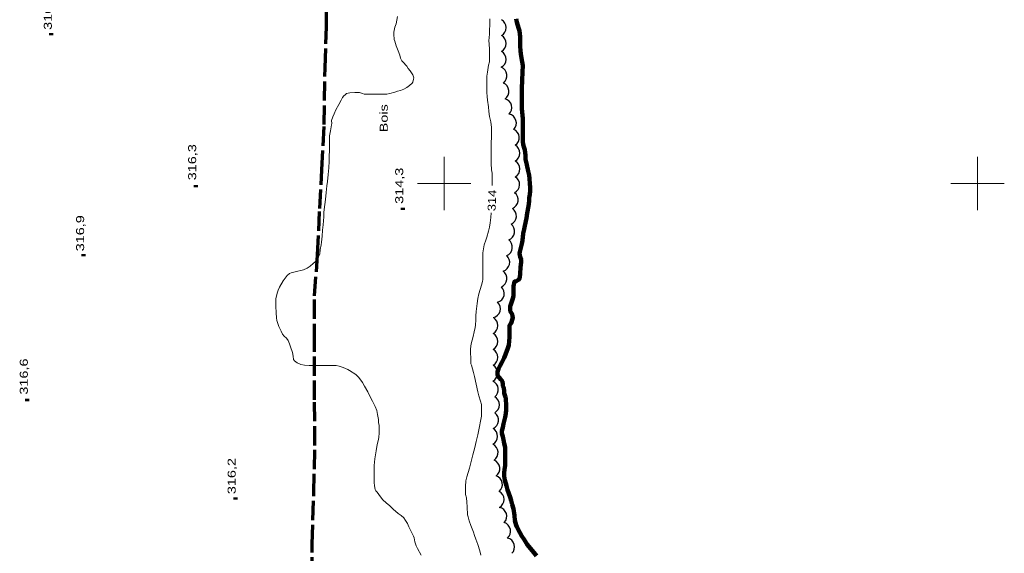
# Model space of a CAD drawing. Extents: x 240591 to 242335, y 5323482 to 5326937.
# Drawn here: x 241641 to 242010, y 5325061.4 to 5325261.4 of the extents above; entities that cross this region are included whole.
import ezdxf
from ezdxf.enums import TextEntityAlignment as Align

# ---------------------------------------------------------------- set-up
doc = ezdxf.new("R2010")
doc.units = 0
doc.header["$LTSCALE"] = 1.2
doc.linetypes.add('DASH_DOUBLE_DOT', pattern=[9.2, 5, -1.2, 0.3, -1.2, 0.3, -1.2])
doc.linetypes.add('LONG_DASHED', pattern=[7.5, 6, -1.5])
for name, color, linetype, lineweight in [('2', 7, 'Continuous', 13), ('22', 7, 'LONG_DASHED', 70), ('3', 7, 'Continuous', 140), ('4', 7, 'DASH_DOUBLE_DOT', 53), ('44', 7, 'Continuous', 25), ('61', 7, 'Continuous', 13)]:
    doc.layers.add(name, color=color, linetype=linetype, lineweight=lineweight)

msp = doc.modelspace()

# ---------------------------------------------------------------- linework, layer by layer
at = {"layer": '2', "linetype": 'LONG_DASHED'}
for points in [[(241782.5, 5325262.6), (241782.3, 5325261.3), (241782, 5325259.9), (241781.6, 5325258.6), (241781.2, 5325256.7), (241781.2, 5325256), (241781.3, 5325254), (241781.5, 5325253.4), (241782.1, 5325251.6), (241782.8, 5325249.8), (241783.4, 5325248.1), (241783.7, 5325247), (241784.2, 5325246), (241784.5, 5325245.6), (241786, 5325244), (241786.6, 5325243.1), (241787.3, 5325242.2), (241788.3, 5325240.7), (241788.7, 5325239.6), (241788.6, 5325239.1), (241788.3, 5325238), (241788, 5325237.6)], [(241817.2, 5325261.7), (241817.2, 5325259.2), (241817.1, 5325257.8), (241817, 5325256), (241816.8, 5325253.5), (241816.9, 5325252.4), (241817, 5325250.3), (241817, 5325248.3), (241817, 5325245.6), (241816.7, 5325244.4), (241816.3, 5325241.8), (241816.1, 5325240.3), (241816.1, 5325239), (241816.1, 5325237.1), (241816.1, 5325234.1), (241816.2, 5325232.6), (241816.3, 5325231.3), (241816.7, 5325228.8), (241816.8, 5325227), (241817.1, 5325225.1), (241817.5, 5325223.1), (241817.8, 5325221), (241817.8, 5325220.1), (241817.8, 5325217.5), (241817.7, 5325215.2), (241817.7, 5325213.4), (241817.7, 5325210.5), (241817.7, 5325207.5), (241817.8, 5325205.1), (241818, 5325203.9), (241818, 5325202.3), (241818, 5325199.7), (241818, 5325199.3)], [(241788, 5325237.6), (241787.1, 5325236.8), (241786, 5325236), (241784.9, 5325235.4), (241783.7, 5325234.9), (241782.5, 5325234.6), (241781.5, 5325234.3), (241779.7, 5325233.8), (241778.6, 5325233.5), (241777.4, 5325233.5), (241775.4, 5325233.5), (241772.6, 5325233.5), (241770.1, 5325233.5), (241769.4, 5325233.7), (241768.3, 5325234.1), (241767.6, 5325234.1), (241766.6, 5325234.1), (241764.7, 5325234), (241763.5, 5325233.7), (241762.9, 5325233.3), (241762.5, 5325232.9), (241762, 5325232.2), (241761.4, 5325231.2), (241760.6, 5325229.6), (241759.5, 5325227.7), (241758.8, 5325226.1), (241758.3, 5325225), (241757.8, 5325223.7)], [(241757.8, 5325223.7), (241757.9, 5325222.5), (241757.8, 5325222), (241757.5, 5325219.8), (241757.1, 5325217.9), (241757.1, 5325217), (241757.1, 5325215.2), (241757.1, 5325212.5), (241757, 5325210.1), (241756.9, 5325208.4), (241756.8, 5325205.9), (241756.6, 5325203.4), (241756.3, 5325200.8), (241756.1, 5325199.2), (241755.8, 5325196.6), (241755.6, 5325194), (241755.3, 5325192.1), (241755, 5325189.3), (241754.9, 5325187.6), (241754.7, 5325184.6), (241754.4, 5325182.5), (241754.3, 5325180.3), (241754.1, 5325178), (241753.9, 5325177.1), (241753.6, 5325175.3), (241753.4, 5325173.7), (241753, 5325172.6), (241752.5, 5325171.6), (241751.7, 5325170.7), (241750.9, 5325170), (241749.8, 5325169.1), (241748.7, 5325168.3), (241747.3, 5325167.7), (241746.3, 5325167.4), (241745.2, 5325167.2), (241742.7, 5325166.6), (241742.1, 5325166.3), (241741.2, 5325165.6), (241740.4, 5325164.6), (241739.7, 5325163.5), (241738.3, 5325161.2), (241737.8, 5325160), (241737.5, 5325158.9), (241737, 5325156.8), (241737, 5325155.5), (241737, 5325154), (241737.1, 5325151.5), (241737.2, 5325149.7), (241737.3, 5325148.7), (241737.7, 5325147.6), (241738.1, 5325146.4), (241738.9, 5325144.7), (241739.5, 5325143.6), (241740.1, 5325142.8), (241740.9, 5325142.1), (241741.6, 5325141.2), (241742.1, 5325140), (241742.5, 5325138.8), (241743.2, 5325136.7), (241743.4, 5325135.3), (241743.6, 5325134.1), (241744, 5325133.6), (241745, 5325132.8), (241746.3, 5325132.2), (241747.7, 5325131.9), (241749.4, 5325131.8), (241750.8, 5325131.8), (241754, 5325131.8), (241756.8, 5325131.8), (241759.6, 5325131.8), (241760.7, 5325131.6), (241762.2, 5325131.1), (241764, 5325130.3), (241764.6, 5325129.9), (241766.9, 5325128.4), (241768, 5325127.4), (241768.5, 5325126.8), (241769.4, 5325125.5), (241770.2, 5325124.1), (241771.4, 5325121.9), (241772.1, 5325120.6), (241773.2, 5325118.5), (241774.2, 5325116.4), (241774.8, 5325115), (241775.1, 5325113.5), (241775.4, 5325111.6), (241775.5, 5325110.5), (241775.7, 5325109.4), (241775.7, 5325108.1), (241775.7, 5325106.6), (241775.6, 5325104.8), (241775.3, 5325103.6), (241775, 5325102.2), (241774.6, 5325099.9), (241774.1, 5325096.8), (241773.8, 5325094.4), (241773.8, 5325093.5), (241773.8, 5325090.8), (241773.8, 5325088), (241773.9, 5325086.7), (241774.2, 5325085.4)], [(241817.7, 5325189), (241817.5, 5325187.3), (241817.3, 5325185.3), (241817, 5325183.7), (241816.7, 5325182.2), (241816.1, 5325179.9), (241815.7, 5325178.8), (241815.1, 5325177), (241814.8, 5325175.5), (241814.6, 5325174), (241814.6, 5325172.3), (241814.6, 5325169.7), (241814.6, 5325167), (241814.6, 5325164), (241814.4, 5325163.3), (241814, 5325161.9), (241813.1, 5325158.7), (241812.7, 5325156.9), (241812.4, 5325155), (241812, 5325152.1), (241811.9, 5325150.4), (241811.9, 5325148.9), (241811.8, 5325146.9), (241811.7, 5325146.1), (241811.3, 5325144.5), (241810.9, 5325142.7), (241810.2, 5325140), (241809.9, 5325138.1), (241809.9, 5325137.1), (241810, 5325134.1), (241810.1, 5325132.5), (241810.3, 5325131.9), (241811.1, 5325129.2), (241811.4, 5325127.7), (241812, 5325124.8)], [(241812, 5325124.8), (241812.7, 5325121.9), (241813.1, 5325120.4), (241813.7, 5325118.4), (241814, 5325117.2), (241814.1, 5325116), (241814.1, 5325114.5), (241814, 5325112.8), (241813.7, 5325110.9), (241813.3, 5325109), (241812.7, 5325105.9), (241812.1, 5325103.3), (241811.6, 5325101.1), (241810.8, 5325098.3), (241810.2, 5325095.8), (241809.5, 5325093.3), (241809, 5325091.7), (241808.5, 5325090.1), (241808.2, 5325088.6), (241808, 5325086.5), (241808, 5325085.3), (241808.1, 5325083.5), (241808.4, 5325082.2), (241808.6, 5325080.6), (241808.7, 5325078.9), (241808.8, 5325075.9), (241809, 5325075.1), (241809.4, 5325073.6), (241810, 5325071.8), (241810.6, 5325070.6), (241811.1, 5325069.4), (241811.4, 5325068.1), (241811.9, 5325066.8), (241812.7, 5325064.7), (241813.4, 5325062.4), (241813.8, 5325060.7)], [(241774.2, 5325085.4), (241774.5, 5325084.9), (241774.9, 5325084.3), (241776.2, 5325082.6), (241777.1, 5325081.5), (241778.3, 5325080.4), (241779.7, 5325079.2), (241781, 5325078), (241782.8, 5325076.4), (241783.9, 5325075.6), (241784.9, 5325074.7), (241785.6, 5325073.7), (241786.3, 5325072.6), (241786.8, 5325071.4), (241787.9, 5325069.1), (241788.6, 5325067.9), (241788.8, 5325067.2), (241789.1, 5325065.7), (241789.5, 5325064.3), (241790.1, 5325063.2), (241791.4, 5325060.7)]]:
    msp.add_lwpolyline(points, dxfattribs=at)
at = {"layer": '22'}
msp.add_lwpolyline([(241750.3, 5325043.8), (241750.6, 5325064.9), (241751.2, 5325084), (241751.6, 5325101.9), (241751.5, 5325119), (241751.4, 5325140.3), (241751.5, 5325157.9), (241752.6, 5325173.3), (241753.4, 5325190.6), (241754.2, 5325205.2), (241755.1, 5325222.1), (241755.4, 5325243.4), (241756, 5325258.8), (241756, 5325268.5)], dxfattribs=at)
at = {"layer": '3'}
for p, q in [((241652.8, 5325255.6), (241652.8, 5325256.4)), ((241707, 5325198.6), (241707, 5325199.4)), ((241784.5, 5325190.1), (241784.5, 5325190.9)), ((241664.9, 5325172.8), (241664.9, 5325173.6)), ((241643.8, 5325118.5), (241643.8, 5325119.3)), ((241721.8, 5325081.6), (241721.8, 5325082.4))]:
    msp.add_line(p, q, dxfattribs=at)
at = {"layer": '4', "linetype": 'Continuous', "lineweight": 90}
for points in [[(241824.5, 5325144.6), (241824.5, 5325146.4), (241824.6, 5325147), (241825, 5325147.5), (241825.3, 5325148.1), (241825.8, 5325149.8), (241825.7, 5325150.3), (241825.5, 5325151), (241824.8, 5325152.2), (241824.8, 5325152.7), (241824.8, 5325154), (241825, 5325154.7), (241825.7, 5325156.5), (241826, 5325157.8), (241826, 5325159), (241826, 5325161.6), (241826.4, 5325163.3), (241827, 5325163.4), (241827.9, 5325163.9), (241828.3, 5325164.4), (241828.4, 5325164.9), (241828.5, 5325166.2), (241828.7, 5325168.7), (241828.9, 5325170.5), (241828.9, 5325171.6), (241828.6, 5325172.5), (241828.3, 5325173.8), (241828.4, 5325174.4), (241828.5, 5325174.9), (241829.2, 5325177.4), (241829.4, 5325178.7), (241829.7, 5325181.3), (241830, 5325182.9), (241830.3, 5325184.2), (241830.9, 5325187), (241831.2, 5325188.9), (241831.7, 5325191.5), (241831.9, 5325193.4), (241831.9, 5325194.6), (241832.2, 5325195.9), (241832.3, 5325197.3), (241832.3, 5325198.7), (241832.1, 5325199.9), (241832, 5325201.9), (241831.9, 5325203.2), (241831.5, 5325204.7), (241831, 5325207), (241830.5, 5325209.1), (241830.5, 5325210.5), (241830.3, 5325212.7), (241830, 5325213.4), (241829.7, 5325214.6), (241829.6, 5325215.8), (241829.6, 5325217), (241829.6, 5325220.2), (241829.6, 5325222.9), (241829.5, 5325224.3), (241829.4, 5325225.7), (241829.2, 5325228), (241829.2, 5325229.7), (241829.2, 5325232.8), (241829.2, 5325235.6), (241829.3, 5325238.7), (241829.4, 5325241.7), (241829.5, 5325244.3), (241829.3, 5325245.6), (241828.8, 5325248.5), (241828.7, 5325249.9), (241828.6, 5325251.4), (241828.6, 5325252.8), (241828.6, 5325255), (241828.3, 5325257.3), (241827.9, 5325258.4), (241827.3, 5325260.5), (241827.1, 5325261.7)], [(241834.6, 5325060.5), (241833.7, 5325061.7), (241832.4, 5325063.3), (241831.2, 5325064.8), (241830, 5325066.6), (241829.2, 5325067.9), (241828.4, 5325069.2), (241827.3, 5325071.3), (241827, 5325072), (241826.6, 5325073.7), (241826.4, 5325075.6), (241826, 5325078.1), (241825.6, 5325079.7), (241825.2, 5325081.2), (241824.8, 5325082.5), (241823.8, 5325085.2), (241823.4, 5325086.7), (241822.8, 5325088.9), (241822.6, 5325090.3), (241822.5, 5325091.6), (241822.7, 5325092.9), (241822.9, 5325094.4), (241822.9, 5325095.8), (241822.9, 5325098.4), (241822.9, 5325101.2), (241822.6, 5325102.6), (241822.3, 5325104), (241822, 5325105.2), (241821.7, 5325106.3), (241821.7, 5325107.4), (241822, 5325108.6), (241822.3, 5325109.9), (241822.9, 5325112.4), (241823.2, 5325113.8), (241823.3, 5325115.2), (241823.3, 5325116.7), (241823.2, 5325119.4), (241823, 5325119.9), (241822.5, 5325121.5), (241822.5, 5325122.2), (241822.4, 5325123.5), (241822.1, 5325124.1), (241822, 5325124.7), (241821.9, 5325125.8), (241821.7, 5325126.2), (241821.3, 5325126.6), (241820.1, 5325128.1), (241820, 5325128.8), (241820, 5325129.4), (241820.4, 5325130.6), (241821, 5325131.8), (241821.7, 5325133), (241822.6, 5325134.7), (241823.1, 5325135.9), (241823.9, 5325138.3), (241824.3, 5325139.5), (241824.4, 5325140.9), (241824.5, 5325142.4), (241824.5, 5325144.6)]]:
    msp.add_lwpolyline(points, dxfattribs=at)
at = {"layer": '44'}
for centre, radius, start, end in [((241822.044, 5325228.477), 3.397, 313.67077, 75.75749), ((241824.94, 5325199.63), 3.403, 296.72203, 58.45794), ((241824.432, 5325193.87), 3.399, 291.17613, 53.16333), ((241816.766, 5325134.895), 3.404, 299.0688, 60.93119), ((241819.098, 5325081.602), 3.413, 300.11391, 61.80858), ((241820.117, 5325075.322), 3.399, 316.44032, 78.2332), ((241821.565, 5325069.729), 3.406, 310.79091, 72.65931), ((241823.044, 5325063.829), 3.404, 315.44062, 77.34933)]:
    msp.add_arc(centre, radius, start, end, dxfattribs=at)
for centre, major_axis, ratio, start_param, end_param in [((241819.874, 5325258.45), (3.396, 0), 0.999909, 5.2183457, 7.3480249), ((241819.862, 5325252.505), (3.401, -0.222), 0.999115, 5.2854962, 7.4108615), ((241819.84, 5325246.574), (3.4, -0.048), 0.999859, 5.219818, 7.3515117), ((241820.198, 5325240.418), (3.371, 0.458), 0.999638, 5.2175023, 7.3421705), ((241820.916, 5325234.55), (3.385, 0.369), 0.999797, 5.2189869, 7.3491912), ((241823.699, 5325222.676), (3.262, 1.01), 0.99986, 5.2212193, 7.3501784), ((241824.798, 5325217.213), (-1.981, 2.759), 0.999995, 3.1135274, 5.2446031), ((241825.04, 5325211.433), (3.4, 0), 0.999977, 5.2191058, 7.3438982), ((241825.046, 5325205.487), (3.404, 0.029), 0.997501, 5.2179345, 7.3413801), ((241823.737, 5325187.898), (-1.44, 3.078), 0.999994, 3.1199239, 5.2438999), ((241823.025, 5325182.094), (3.376, -0.489), 0.998892, 5.2203519, 7.3400894), ((241822.219, 5325176.173), (3.357, -0.584), 0.998263, 5.2697725, 7.3909782), ((241821.224, 5325170.491), (-1.026, 3.244), 0.999995, 3.1141745, 5.2441578), ((241820.191, 5325164.448), (3.379, -0.379), 0.999994, 5.2192058, 7.3479424), ((241819.191, 5325158.81), (3.309, -0.798), 0.999638, 5.2192803, 7.3451295), ((241817.688, 5325153.093), (-0.878, 3.314), 0.999995, 3.1186806, 5.2440064), ((241816.811, 5325146.804), (3.399, -0.048), 0.999977, 5.2197144, 7.3516158), ((241816.775, 5325140.84), (3.395, 0), 0.999994, 5.2182714, 7.3480994), ((241816.682, 5325128.987), (3.408, -0.097), 0.99991, 5.218757, 7.3475467), ((241816.977, 5325122.813), (3.371, 0.448), 0.997498, 5.2138866, 7.3385575), ((241817.331, 5325117.102), (-2.968, 1.676), 0.999983, 2.5965224, 4.7184096), ((241817.03, 5325111.351), (3.389, -0.361), 0.998892, 5.2223587, 7.3440697), ((241816.654, 5325105.281), (3.397, -0.258), 0.998807, 5.2790583, 7.4017805), ((241816.877, 5325099.179), (3.383, 0.291), 0.999949, 5.218065, 7.3486804), ((241817.504, 5325093.201), (-2.081, 2.692), 0.999994, 3.1175666, 5.2441019), ((241818.499, 5325087.206), (3.408, -0.118), 0.999927, 5.4525245, 7.584602)]:
    msp.add_ellipse(centre, major_axis=major_axis, ratio=ratio, start_param=start_param, end_param=end_param, dxfattribs=at)
at = {"layer": '61'}
for points in [[(241800, 5325210), (241800, 5325200), (241800, 5325190)], [(242000, 5325210), (242000, 5325200), (242000, 5325190)], [(241790, 5325200), (241800, 5325200), (241810, 5325200)], [(241990, 5325200), (242000, 5325200), (242010, 5325200)]]:
    msp.add_lwpolyline(points, dxfattribs=at)

# ---------------------------------------------------------------- texts
at = {"layer": '2', "width": 1.2}
msp.add_text('314', height=3, rotation=87.71, dxfattribs=at).set_placement((241819.3, 5325189.6))
at = {"layer": '3', "width": 1.35}
for s, p in [('316,6', (241653, 5325257.6)), ('314,3', (241784.7, 5325192.4)), ('316,9', (241665.1, 5325174.6)), ('316,6', (241644, 5325120.9)), ('316,2', (241721.9, 5325083.6))]:
    msp.add_text(s, height=3, rotation=90, dxfattribs=at).set_placement(p)
msp.add_text('316,3', height=3, rotation=90, dxfattribs=at).set_placement((241707.1, 5325208), align=Align.CENTER)
at = {"layer": '44', "width": 1.35}
msp.add_text('Bois', height=3, rotation=90, dxfattribs=at).set_placement((241778.9, 5325219.2))

doc.saveas('drawing.dxf')
